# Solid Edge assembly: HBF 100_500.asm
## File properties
Title: Zylinder
Author: ahadarics
Template: iso assembly.asm
Last saved by: ahadarics
Revision: 49
Application: Solid Edge
Username: ahadarics
Dokumentum tartalom típus: 1
Document Number: HBF 100/500
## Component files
Kit.par
Profilrohr 100_500.par
Kolbenstange_1_100_500.par
Mutter.par
Kolbenstange_2_100_500.par
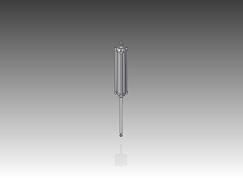
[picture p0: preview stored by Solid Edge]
